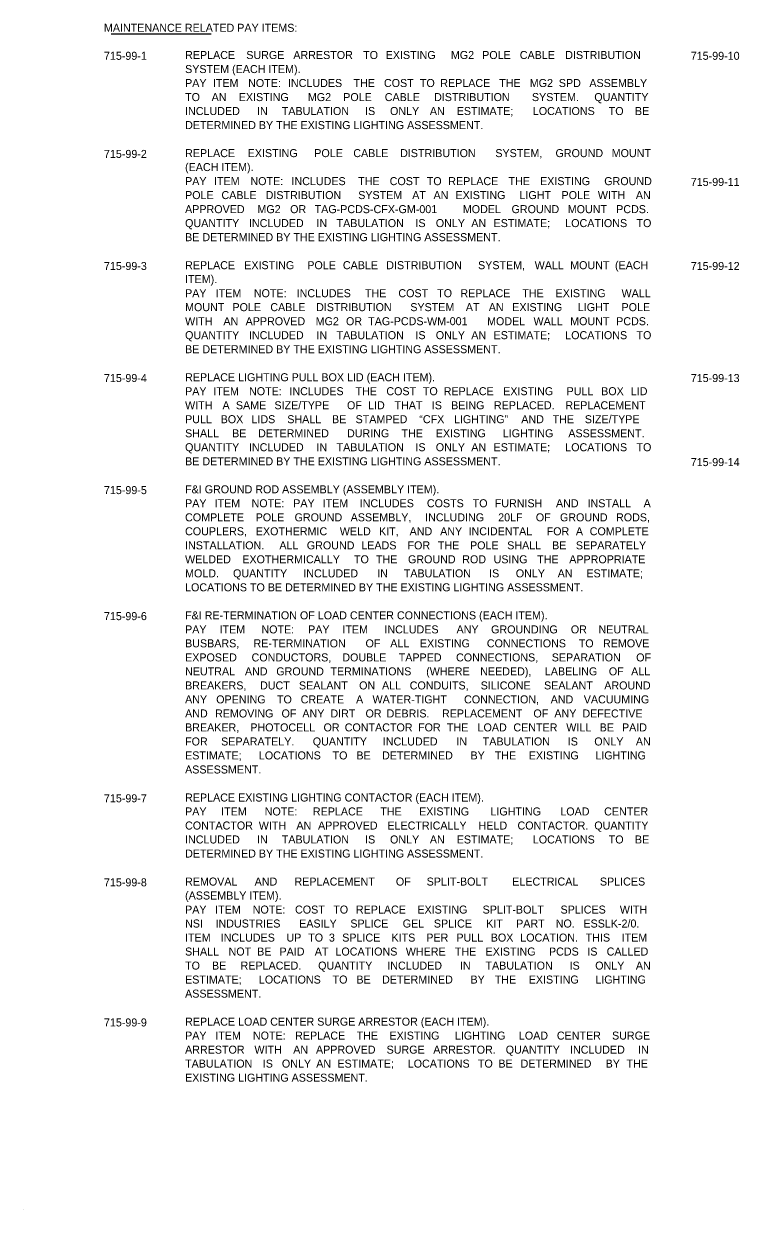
# Model space of a CAD drawing. Extents: x -55 to 2471539, y -90 to 3608906.
# Drawn here: x -55 to 570, y -90 to 947 of the extents above; entities that cross this region are included whole.
import ezdxf

# ---------------------------------------------------------------- set-up
doc = ezdxf.new("R2010")
doc.units = 0
doc.layers.add('AdhocPoint_dp', color=7, linetype='Continuous')
doc.layers.add('TextNotes', color=7, linetype='Continuous')

msp = doc.modelspace()

# ---------------------------------------------------------------- linework, layer by layer
at = {"layer": 'AdhocPoint_dp'}
msp.add_line((-55, -90), (-55, -90), dxfattribs=at)
at = {"layer": 'TextNotes'}
msp.add_line((21.5, 937.9), (108.8, 937.9), dxfattribs=at)

# ---------------------------------------------------------------- texts
for s, p in [('MAINTENANCE RELATED PAY ITEMS:', (15.1, 939.7)), ('REPLACE ', (86, 915.9)), ('SURGE ', (139.5, 915.9)), ('ARRESTOR ', (180.6, 915.9)), ('TO ', (241.6, 915.9)), ('EXISTING ', (261.3, 915.9)), ('MG2 ', (318.3, 915.9)), ('POLE ', (345.6, 915.9)), ('CABLE ', (378.5, 915.9)), ('DISTRIBUTION ', (418.2, 915.9)), ('715-99-1', (15.1, 915.2)), ('715-99-10', (527.9, 915.2)), ('SYSTEM (EACH ITEM).', (86, 903.6)), ('PAY ', (86, 891.4)), ('ITEM ', (110.3, 891.4)), ('NOTE: ', (141.1, 891.4)), ('INCLUDES ', (175.9, 891.4)), ('THE ', (233.2, 891.4)), ('COST ', (259.8, 891.4)), ('TO ', (291.2, 891.4)), ('REPLACE ', (309, 891.4)), ('THE ', (360.5, 891.4)), ('MG2 ', (387.2, 891.4)), ('SPD ', (412.6, 891.4)), ('ASSEMBLY ', (439.3, 891.4)), ('TO ', (86, 879.1)), ('AN ', (109.2, 879.1)), ('EXISTING ', (132.9, 879.1)), ('MG2 ', (193.3, 879.1)), ('POLE ', (224.2, 879.1)), ('CABLE ', (260.5, 879.1)), ('DISTRIBUTION ', (303.6, 879.1)), ('SYSTEM. ', (389.1, 879.1)), ('QUANTITY ', (443.6, 879.1)), ('INCLUDED ', (86, 866.9)), ('IN ', (148.9, 866.9)), ('TABULATION ', (170.5, 866.9)), ('IS ', (243.3, 866.9)), ('ONLY ', (265.1, 866.9)), ('AN ', (299.9, 866.9)), ('ESTIMATE; ', (323.4, 866.9)), ('LOCATIONS ', (389.9, 866.9)), ('TO ', (456.2, 866.9)), ('BE ', (479.1, 866.9)), ('DETERMINED BY THE EXISTING LIGHTING ASSESSMENT.', (86, 854.6)), ('715-99-2', (15.1, 829.4)), ('REPLACE ', (86, 830.1)), ('EXISTING ', (140.7, 830.1)), ('POLE ', (198.9, 830.1)), ('CABLE ', (233, 830.1)), ('DISTRIBUTION ', (273.9, 830.1)), ('SYSTEM, ', (357.1, 830.1)), ('GROUND ', (409.7, 830.1)), ('MOUNT ', (458.8, 830.1)), ('(EACH ITEM).', (86, 817.9)), ('PAY ', (86, 805.6)), ('ITEM ', (111.3, 805.6)), ('NOTE: ', (143.1, 805.6)), ('INCLUDES ', (179, 805.6)), ('THE ', (237.2, 805.6)), ('COST ', (264.8, 805.6)), ('TO ', (297.2, 805.6)), ('REPLACE ', (316, 805.6)), ('THE ', (368.6, 805.6)), ('EXISTING ', (396.2, 805.6)), ('GROUND ', (452.3, 805.6)), ('715-99-11', (527.9, 804.9)), ('POLE ', (86, 793.4)), ('CABLE ', (117.8, 793.4)), ('DISTRIBUTION ', (156.4, 793.4)), ('SYSTEM ', (237.3, 793.4)), ('AT ', (284.5, 793.4)), ('AN ', (303.1, 793.4)), ('EXISTING ', (322.3, 793.4)), ('LIGHT ', (378.2, 793.4)), ('POLE ', (415, 793.4)), ('WITH ', (446.7, 793.4)), ('AN ', (479.9, 793.4)), ('APPROVED ', (86, 781.1)), ('MG2 ', (149.2, 781.1)), ('OR ', (177.8, 781.1)), ('TAG-PCDS-CFX-GM-001 ', (199.2, 781.1)), ('MODEL ', (328.7, 781.1)), ('GROUND ', (371.3, 781.1)), ('MOUNT ', (420.4, 781.1)), ('PCDS. ', (462.7, 781.1)), ('QUANTITY ', (86, 768.9)), ('INCLUDED ', (141.8, 768.9)), ('IN ', (200.8, 768.9)), ('TABULATION ', (218.4, 768.9)), ('IS ', (287.3, 768.9)), ('ONLY ', (305.1, 768.9)), ('AN ', (336.1, 768.9)), ('ESTIMATE; ', (355.6, 768.9)), ('LOCATIONS ', (418.2, 768.9)), ('TO ', (480.5, 768.9)), ('BE DETERMINED BY THE EXISTING LIGHTING ASSESSMENT.', (86, 756.6)), ('715-99-3', (15.1, 731.4)), ('REPLACE ', (86, 732.1)), ('EXISTING ', (137.7, 732.1)), ('POLE ', (192.8, 732.1)), ('CABLE ', (223.9, 732.1)), ('DISTRIBUTION ', (261.8, 732.1)), ('SYSTEM, ', (342, 732.1)), ('WALL ', (391.5, 732.1)), ('MOUNT ', (422.5, 732.1)), ('(EACH ', (461.7, 732.1)), ('715-99-12', (527.9, 731.4)), ('ITEM).', (86, 719.9)), ('PAY ', (86, 707.6)), ('ITEM ', (112.8, 707.6)), ('NOTE: ', (146.1, 707.6)), ('INCLUDES ', (183.5, 707.6)), ('THE ', (243.2, 707.6)), ('COST ', (272.4, 707.6)), ('TO ', (306.3, 707.6)), ('REPLACE ', (326.6, 707.6)), ('THE ', (380.7, 707.6)), ('EXISTING ', (409.8, 707.6)), ('WALL ', (467.4, 707.6)), ('MOUNT ', (86, 695.4)), ('POLE ', (127.4, 695.4)), ('CABLE ', (160.5, 695.4)), ('DISTRIBUTION ', (200.5, 695.4)), ('SYSTEM ', (282.8, 695.4)), ('AT ', (331.3, 695.4)), ('AN ', (351.4, 695.4)), ('EXISTING ', (371.9, 695.4)), ('LIGHT ', (429.2, 695.4)), ('POLE ', (467.4, 695.4)), ('WITH ', (86, 683.1)), ('AN ', (119.5, 683.1)), ('APPROVED ', (138.9, 683.1)), ('MG2 ', (200.1, 683.1)), ('OR ', (226.6, 683.1)), ('TAG-PCDS-WM-001 ', (246, 683.1)), ('MODEL ', (349.9, 683.1)), ('WALL ', (390.5, 683.1)), ('MOUNT ', (422.5, 683.1)), ('PCDS. ', (462.7, 683.1)), ('QUANTITY ', (86, 670.9)), ('INCLUDED ', (141.8, 670.9)), ('IN ', (200.8, 670.9)), ('TABULATION ', (218.4, 670.9)), ('IS ', (287.3, 670.9)), ('ONLY ', (305.1, 670.9)), ('AN ', (336.1, 670.9)), ('ESTIMATE; ', (355.6, 670.9)), ('LOCATIONS ', (418.2, 670.9)), ('TO ', (480.5, 670.9)), ('BE DETERMINED BY THE EXISTING LIGHTING ASSESSMENT.', (86, 658.6)), ('715-99-4', (15.1, 633.4)), ('REPLACE LIGHTING PULL BOX LID (EACH ITEM).', (86, 634.1)), ('715-99-13', (527.9, 633.4)), ('PAY ', (86, 621.9)), ('ITEM ', (110.7, 621.9)), ('NOTE: ', (141.9, 621.9)), ('INCLUDES ', (177.2, 621.9)), ('THE ', (234.9, 621.9)), ('COST ', (261.9, 621.9)), ('TO ', (293.8, 621.9)), ('REPLACE ', (312, 621.9)), ('EXISTING ', (364, 621.9)), ('PULL ', (419.4, 621.9)), ('BOX ', (449.6, 621.9)), ('LID ', (475.5, 621.9)), ('WITH ', (86, 609.6)), ('A ', (118.7, 609.6)), ('SAME ', (130.4, 609.6)), ('SIZE/TYPE ', (164.1, 609.6)), ('OF ', (227.5, 609.6)), ('LID ', (245.9, 609.6)), ('THAT ', (269, 609.6)), ('IS ', (301.6, 609.6)), ('BEING ', (318.5, 609.6)), ('REPLACED. ', (355.9, 609.6)), ('REPLACEMENT ', (418.3, 609.6)), ('PULL ', (86, 597.4)), ('BOX ', (117.1, 597.4)), ('LIDS ', (144, 597.4)), ('SHALL ', (175.3, 597.4)), ('BE ', (214.4, 597.4)), ('STAMPED ', (235, 597.4)), ('“CFX ', (290.7, 597.4)), ('LIGHTING” ', (321, 597.4)), ('AND ', (379.8, 597.4)), ('THE ', (407.2, 597.4)), ('SIZE/TYPE ', (435.3, 597.4)), ('SHALL ', (86, 585.1)), ('BE ', (127.1, 585.1)), ('DETERMINED ', (149.8, 585.1)), ('DURING ', (227.5, 585.1)), ('THE ', (275.1, 585.1)), ('EXISTING ', (305.1, 585.1)), ('LIGHTING ', (363.6, 585.1)), ('ASSESSMENT. ', (420.9, 585.1)), ('QUANTITY ', (86, 572.9)), ('INCLUDED ', (141.8, 572.9)), ('IN ', (200.8, 572.9)), ('TABULATION ', (218.4, 572.9)), ('IS ', (287.3, 572.9)), ('ONLY ', (305.1, 572.9)), ('AN ', (336.1, 572.9)), ('ESTIMATE; ', (355.6, 572.9)), ('LOCATIONS ', (418.2, 572.9)), ('TO ', (480.5, 572.9)), ('BE DETERMINED BY THE EXISTING LIGHTING ASSESSMENT.', (86, 560.6)), ('715-99-14', (527.9, 559.9)), ('715-99-5', (15.1, 535.4)), ('F&I GROUND ROD ASSEMBLY (ASSEMBLY ITEM).', (86, 536.1)), ('PAY ', (86, 523.9)), ('ITEM ', (111.8, 523.9)), ('NOTE: ', (144.1, 523.9)), ('PAY ', (180.5, 523.9)), ('ITEM ', (206.2, 523.9)), ('INCLUDES ', (238.6, 523.9)), ('COSTS ', (297.3, 523.9)), ('TO ', (337.3, 523.9)), ('FURNISH ', (356.6, 523.9)), ('AND ', (410.1, 523.9)), ('INSTALL ', (437.7, 523.9)), ('A ', (486.7, 523.9)), ('COMPLETE ', (86, 511.6)), ('POLE ', (147.7, 511.6)), ('GROUND ', (181.7, 511.6)), ('ASSEMBLY, ', (230.7, 511.6)), ('INCLUDING ', (295.8, 511.6)), ('20LF ', (359.6, 511.6)), ('OF ', (392.5, 511.6)), ('GROUND ', (413.6, 511.6)), ('RODS, ', (462.6, 511.6)), ('COUPLERS, ', (86, 499.4)), ('EXOTHERMIC ', (147.8, 499.4)), ('WELD ', (221.2, 499.4)), ('KIT, ', (255.5, 499.4)), ('AND ', (282.2, 499.4)), ('ANY ', (308.9, 499.4)), ('INCIDENTAL ', (333.7, 499.4)), ('FOR ', (402, 499.4)), ('A ', (427.5, 499.4)), ('COMPLETE ', (439.6, 499.4)), ('INSTALLATION. ', (86, 487.1)), ('ALL ', (168.4, 487.1)), ('GROUND ', (192.4, 487.1)), ('LEADS ', (240, 487.1)), ('FOR ', (280.4, 487.1)), ('THE ', (306.9, 487.1)), ('POLE ', (335, 487.1)), ('SHALL ', (367.5, 487.1)), ('BE ', (406.7, 487.1)), ('SEPARATELY ', (427.5, 487.1)), ('WELDED ', (86, 474.9)), ('EXOTHERMICALLY ', (136, 474.9)), ('TO ', (233.6, 474.9)), ('THE ', (252.8, 474.9)), ('GROUND ', (280.8, 474.9)), ('ROD ', (328.2, 474.9)), ('USING ', (355.6, 474.9)), ('THE ', (393.7, 474.9)), ('APPROPRIATE ', (421.7, 474.9)), ('MOLD. ', (86, 462.6)), ('QUANTITY ', (127.9, 462.6)), ('INCLUDED ', (189.3, 462.6)), ('IN ', (253.9, 462.6)), ('TABULATION ', (277.1, 462.6)), ('IS ', (351.7, 462.6)), ('ONLY ', (375, 462.6)), ('AN ', (411.6, 462.6)), ('ESTIMATE; ', (436.7, 462.6)), ('LOCATIONS TO BE DETERMINED BY THE EXISTING LIGHTING ASSESSMENT.', (86, 450.4)), ('715-99-6', (15.1, 425.2)), ('F&I RE-TERMINATION OF LOAD CENTER CONNECTIONS (EACH ITEM).', (86, 425.9)), ('PAY ', (86, 413.6)), ('ITEM ', (116.1, 413.6)), ('NOTE: ', (152.7, 413.6)), ('PAY ', (193.5, 413.6)), ('ITEM ', (223.5, 413.6)), ('INCLUDES ', (260.2, 413.6)), ('ANY ', (323.2, 413.6)), ('GROUNDING ', (353.4, 413.6)), ('OR ', (423.1, 413.6)), ('NEUTRAL ', (447.3, 413.6)), ('BUSBARS, ', (86, 401.4)), ('RE-TERMINATION ', (145.8, 401.4)), ('OF ', (243.7, 401.4)), ('ALL ', (265.3, 401.4)), ('EXISTING ', (291.2, 401.4)), ('CONNECTIONS ', (349.7, 401.4)), ('TO ', (430, 401.4)), ('REMOVE ', (451.2, 401.4)), ('EXPOSED ', (86, 389.1)), ('CONDUCTORS, ', (144.1, 389.1)), ('DOUBLE ', (223.4, 389.1)), ('TAPPED ', (272.7, 389.1)), ('CONNECTIONS, ', (322.8, 389.1)), ('SEPARATION ', (406.4, 389.1)), ('OF ', (480.2, 389.1)), ('NEUTRAL ', (86, 376.9)), ('AND ', (138.3, 376.9)), ('GROUND ', (165.7, 376.9)), ('TERMINATIONS ', (213, 376.9)), ('(WHERE ', (296.7, 376.9)), ('NEEDED), ', (343.9, 376.9)), ('LABELING ', (400.4, 376.9)), ('OF ', (456.3, 376.9)), ('ALL ', (475.8, 376.9)), ('BREAKERS, ', (86, 364.6)), ('DUCT ', (151.5, 364.6)), ('SEALANT ', (185.5, 364.6)), ('ON ', (238.1, 364.6)), ('ALL ', (258.1, 364.6)), ('CONDUITS, ', (282.3, 364.6)), ('SILICONE ', (344.3, 364.6)), ('SEALANT ', (399.7, 364.6)), ('AROUND ', (452.3, 364.6)), ('ANY ', (86, 352.4)), ('OPENING ', (113.2, 352.4)), ('TO ', (166.3, 352.4)), ('CREATE ', (187, 352.4)), ('A ', (235.4, 352.4)), ('WATER-TIGHT ', (249.8, 352.4)), ('CONNECTION, ', (329.8, 352.4)), ('AND ', (405.5, 352.4)), ('VACUUMING ', (434.4, 352.4)), ('AND ', (86, 340.1)), ('REMOVING ', (112.2, 340.1)), ('OF ', (170.3, 340.1)), ('ANY ', (188.5, 340.1)), ('DIRT ', (213, 340.1)), ('OR ', (243.7, 340.1)), ('DEBRIS. ', (262.1, 340.1)), ('REPLACEMENT ', (310.5, 340.1)), ('OF ', (390.4, 340.1)), ('ANY ', (408.7, 340.1)), ('DEFECTIVE ', (433.2, 340.1)), ('BREAKER, ', (86, 327.9)), ('PHOTOCELL ', (143, 327.9)), ('OR ', (207, 327.9)), ('CONTACTOR ', (225.5, 327.9)), ('FOR ', (289.6, 327.9)), ('THE ', (314.8, 327.9)), ('LOAD ', (341.6, 327.9)), ('CENTER ', (372.9, 327.9)), ('WILL ', (419.1, 327.9)), ('BE ', (448.3, 327.9)), ('PAID ', (467.8, 327.9)), ('FOR ', (86, 315.6)), ('SEPARATELY. ', (117.5, 315.6)), ('QUANTITY ', (197.6, 315.6)), ('INCLUDED ', (258.8, 315.6)), ('IN ', (323.1, 315.6)), ('TABULATION ', (346.1, 315.6)), ('IS ', (420.4, 315.6)), ('ONLY ', (443.6, 315.6)), ('AN ', (479.9, 315.6)), ('ESTIMATE; ', (86, 303.4)), ('LOCATIONS ', (150.5, 303.4)), ('TO ', (214.9, 303.4)), ('BE ', (235.7, 303.4)), ('DETERMINED ', (258.1, 303.4)), ('BY ', (335.4, 303.4)), ('THE ', (356.6, 303.4)), ('EXISTING ', (386.3, 303.4)), ('LIGHTING ', (444.5, 303.4)), ('ASSESSMENT.', (86, 291.1)), ('715-99-7', (15.1, 265.9)), ('REPLACE EXISTING LIGHTING CONTACTOR (EACH ITEM).', (86, 266.6)), ('PAY ', (86, 254.4)), ('ITEM ', (117.5, 254.4)), ('NOTE: ', (155.6, 254.4)), ('REPLACE ', (197.7, 254.4)), ('THE ', (256.6, 254.4)), ('EXISTING ', (290.5, 254.4)), ('LIGHTING ', (352.8, 254.4)), ('LOAD ', (413.9, 254.4)), ('CENTER ', (452.2, 254.4)), ('CONTACTOR ', (86, 242.1)), ('WITH ', (150.4, 242.1)), ('AN ', (183.3, 242.1)), ('APPROVED ', (202.2, 242.1)), ('ELECTRICALLY ', (262.8, 242.1)), ('HELD ', (342.5, 242.1)), ('CONTACTOR. ', (376.5, 242.1)), ('QUANTITY ', (443.6, 242.1)), ('INCLUDED ', (86, 229.9)), ('IN ', (148.9, 229.9)), ('TABULATION ', (170.5, 229.9)), ('IS ', (243.3, 229.9)), ('ONLY ', (265.1, 229.9)), ('AN ', (299.9, 229.9)), ('ESTIMATE; ', (323.4, 229.9)), ('LOCATIONS ', (389.9, 229.9)), ('TO ', (456.2, 229.9)), ('BE ', (479.1, 229.9)), ('DETERMINED BY THE EXISTING LIGHTING ASSESSMENT.', (86, 217.6)), ('715-99-8', (15.1, 192.4)), ('REMOVAL ', (86, 193.1)), ('AND ', (146.8, 193.1)), ('REPLACEMENT ', (181.6, 193.1)), ('OF ', (270.2, 193.1)), ('SPLIT-BOLT ', (297.1, 193.1)), ('ELECTRICAL ', (371.9, 193.1)), ('SPLICES ', (448.5, 193.1)), ('(ASSEMBLY ITEM).', (86, 180.9)), ('PAY ', (86, 168.6)), ('ITEM ', (112.3, 168.6)), ('NOTE: ', (145.1, 168.6)), ('COST ', (182.1, 168.6)), ('TO ', (215.5, 168.6)), ('REPLACE ', (235.3, 168.6)), ('EXISTING ', (289, 168.6)), ('SPLIT-BOLT ', (346, 168.6)), ('SPLICES ', (414.1, 168.6)), ('WITH ', (465.9, 168.6)), ('NSI ', (86, 156.4)), ('INDUSTRIES ', (112.6, 156.4)), ('EASILY ', (185.7, 156.4)), ('SPLICE ', (230.4, 156.4)), ('GEL ', (276.2, 156.4)), ('SPLICE ', (303.4, 156.4)), ('KIT ', (349.2, 156.4)), ('PART ', (375.3, 156.4)), ('NO. ', (409.9, 156.4)), ('ESSLK-2/0. ', (434.1, 156.4)), ('ITEM ', (86, 144.1)), ('INCLUDES ', (117.1, 144.1)), ('UP ', (174.6, 144.1)), ('TO ', (193.6, 144.1)), ('3 ', (211.7, 144.1)), ('SPLICE ', (223.3, 144.1)), ('KITS ', (266.4, 144.1)), ('PER ', (296.8, 144.1)), ('PULL ', (323.1, 144.1)), ('BOX ', (353.1, 144.1)), ('LOCATION. ', (378.9, 144.1)), ('THIS ', (436.1, 144.1)), ('ITEM ', (467.5, 144.1)), ('SHALL ', (86, 131.9)), ('NOT ', (124, 131.9)), ('BE ', (149, 131.9)), ('PAID ', (168.5, 131.9)), ('AT ', (199.3, 131.9)), ('LOCATIONS ', (217.4, 131.9)), ('WHERE ', (278.9, 131.9)), ('THE ', (321.7, 131.9)), ('EXISTING ', (348.6, 131.9)), ('PCDS ', (404, 131.9)), ('IS ', (437.5, 131.9)), ('CALLED ', (454.4, 131.9)), ('TO ', (86, 119.6)), ('BE ', (109.5, 119.6)), ('REPLACED. ', (134.5, 119.6)), ('QUANTITY ', (202.3, 119.6)), ('INCLUDED ', (262.7, 119.6)), ('IN ', (326.2, 119.6)), ('TABULATION ', (348.5, 119.6)), ('IS ', (422, 119.6)), ('ONLY ', (444.4, 119.6)), ('AN ', (479.9, 119.6)), ('ESTIMATE; ', (86, 107.4)), ('LOCATIONS ', (150.5, 107.4)), ('TO ', (214.9, 107.4)), ('BE ', (235.7, 107.4)), ('DETERMINED ', (258.1, 107.4)), ('BY ', (335.4, 107.4)), ('THE ', (356.6, 107.4)), ('EXISTING ', (386.3, 107.4)), ('LIGHTING ', (444.5, 107.4)), ('ASSESSMENT.', (86, 95.1)), ('715-99-9', (15.1, 69.9)), ('REPLACE LOAD CENTER SURGE ARRESTOR (EACH ITEM).', (86, 70.6)), ('PAY ', (86, 58.4)), ('ITEM ', (112.4, 58.4)), ('NOTE: ', (145.3, 58.4)), ('REPLACE ', (182.2, 58.4)), ('THE ', (235.9, 58.4)), ('EXISTING ', (264.6, 58.4)), ('LIGHTING ', (321.8, 58.4)), ('LOAD ', (377.7, 58.4)), ('CENTER ', (410.9, 58.4)), ('SURGE ', (459.1, 58.4)), ('ARRESTOR ', (86, 46.1)), ('WITH ', (146.6, 46.1)), ('AN ', (180.5, 46.1)), ('APPROVED ', (200.4, 46.1)), ('SURGE ', (262.1, 46.1)), ('ARRESTOR. ', (302.9, 46.1)), ('QUANTITY ', (366.2, 46.1)), ('INCLUDED ', (422.4, 46.1)), ('IN ', (481.8, 46.1)), ('TABULATION ', (86, 33.9)), ('IS ', (153.9, 33.9)), ('ONLY ', (170.6, 33.9)), ('AN ', (200.6, 33.9)), ('ESTIMATE; ', (219.1, 33.9)), ('LOCATIONS ', (280.6, 33.9)), ('TO ', (341.9, 33.9)), ('BE ', (359.8, 33.9)), ('DETERMINED ', (379.2, 33.9)), ('BY ', (453.5, 33.9)), ('THE ', (471.7, 33.9)), ('EXISTING LIGHTING ASSESSMENT.', (86, 21.6))]:
    msp.add_text(s, height=7, dxfattribs=at).set_placement(p)

doc.saveas('drawing.dxf')
